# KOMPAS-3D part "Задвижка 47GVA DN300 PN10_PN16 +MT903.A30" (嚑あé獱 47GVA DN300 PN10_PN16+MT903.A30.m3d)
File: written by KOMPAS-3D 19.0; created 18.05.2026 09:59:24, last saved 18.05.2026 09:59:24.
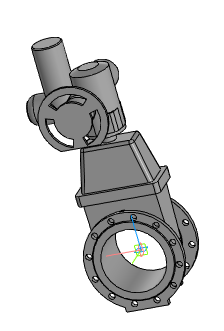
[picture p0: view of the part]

Document properties: Автор: Энергия; Полное имя файла: ..\Задвижка 47GVA DN50_DN1000+MT903.A\Задвижка 47GVA DN300 PN10_PN16+MT903.A30.a3d

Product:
- Part/product: Задвижка 47GVA DN300 PN10_PN16 +MT903.A30
    Масса: 402.009
  - Body: Электропривод МТ903.А30 без блока управления
      Масса: 163.268
  - Body: Задвижка 47GVA DN300 PN10_PN16 без исполнит. мех.
      Масса: 238.74

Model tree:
1. Операция без истории:1
2. Операция без истории:2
